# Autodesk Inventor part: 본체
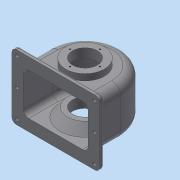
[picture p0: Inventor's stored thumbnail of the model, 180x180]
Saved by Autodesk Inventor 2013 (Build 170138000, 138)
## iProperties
Created: 2015-09
Part Number: 본체
Material: 일반
Document SubType Name: Modeling
Designer: Administrator
Density: 1 g/cm^3
Author: Administrator
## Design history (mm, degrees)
sketch "스케치1"
  geometry: L1 (0, 0)-(0, -47); L2 (0, -47)-(0, 57); L3 (0, -47)-(57, -47); L4 (57, -47)-(57, 0); L5 (0, -47)-(-57, -47); L6 (-57, -47)-(-57, 0); A1 r 57 centre (0, 0) between (57, 0) and (-57, 0)
  constraints: 12 end point, 3 point on circle, 2 perpendicular, 2 tangent, 1 centre point, 1 coincident, 1 collinear, 1 vertical
  dimensions: "d0" = 47 distance of L1.start L1.end; "d1" = 104 distance of L1.end L2.end
extrude "돌출1" new body sketch "스케치1" stored distance "d2" = 77; taper "d3" = 0 deg
fillet "모깎기1" dims "d4" = 14
feature "쉘2" dims "d16" = 5
sketch "스케치5"
  geometry: C1 r 31 at (0, 0); A1 r 43 centre (0, 0) between (43, 0) and (-43, 0) reference
  constraints: 1 centre point, 1 coincident
  dimensions: "d17" = 62 diameter of C1
extrude "돌출4" join sketch "스케치5" distance "d18" = 10; taper "d19" = 0 deg
sketch "스케치6"
  geometry: C1 r 31 at (0, 0) reference; C2 r 20 at (0, 0)
  constraints: 1 centre point, 1 coincident
  dimensions: "d20" = 40 diameter of C2
extrude "돌출5" cut sketch "스케치6" stored distance "d21" = 10; taper "d22" = 0 deg
sketch "스케치7"
  geometry: L1 (-31, 38.5)-(-31, 48.5) reference; L2 (-31, 48.5)-(-20, 48.5) reference; L3 (-20, 48.5)-(-20, 33.5) reference; L4 (-20, 33.5)-(-47, 33.5) reference; L5 (-47, 33.5)-(-47, 38.5) reference; L6 (-47, 38.5)-(-31, 38.5) reference; L7 (57, 24.5)-(57, -24.5) reference; L8 (43, -38.5)-(-47, -38.5) reference; L9 (-47, -38.5)-(-47, -33.5) reference; L10 (-47, -33.5)-(43, -33.5) reference; L11 (52, -24.5)-(52, 24.5) reference; L12 (43, 33.5)-(20, 33.5) reference; L13 (20, 33.5)-(20, 48.5) reference; L14 (20, 48.5)-(31, 48.5) reference; L15 (31, 48.5)-(31, 38.5) reference; L16 (31, 38.5)-(43, 38.5) reference; L17 (0, -19.5)-(28, -19.5); L18 (0, -33.5)-(39.747, -33.5); L19 (28, -19.5)-(39.747, -33.5); L20 (0, -33.5)-(0, -19.5); A1 r 14 centre (43, 24.5) between (57, 24.5) and (43, 38.5) reference; A2 r 14 centre (43, -24.5) between (43, -38.5) and (57, -24.5) reference; A3 r 9 centre (43, -24.5) between (43, -33.5) and (52, -24.5) reference; A4 r 9 centre (43, 24.5) between (52, 24.5) and (43, 33.5) reference; 1 further point
  constraints: 8 end point, 2 point on line, 1 perpendicular
  dimensions: "d24" = 28 distance of L17.start L17.end
revolve "회전1" sketch "스케치7" stored, may be unused: angle "d26" = 90 deg
sketch "스케치8"
  geometry: L1 (-31, 38.5)-(-31, 48.5) reference; L2 (-31, 48.5)-(-20, 48.5) reference; L3 (-20, 48.5)-(-20, 33.5) reference; L4 (-20, 33.5)-(-47, 33.5) reference; L5 (-47, 33.5)-(-47, 38.5) reference; L6 (-47, 38.5)-(-31, 38.5) reference; L7 (57, 24.5)-(57, -24.5) reference; L8 (43, -38.5)-(-47, -38.5) reference; L9 (-47, -38.5)-(-47, -33.5) reference; L10 (-47, -33.5)-(-39.747, -33.5) reference; L11 (-39.747, -33.5)-(-28, -19.5) reference; L12 (-28, -19.5)-(28, -19.5) reference; L13 (28, -19.5)-(39.747, -33.5) reference; L14 (39.747, -33.5)-(43, -33.5) reference; L15 (52, -24.5)-(52, 24.5) reference; L16 (43, 33.5)-(20, 33.5) reference; L17 (20, 33.5)-(20, 48.5) reference; L18 (20, 48.5)-(31, 48.5) reference; L19 (31, 48.5)-(31, 38.5) reference; L20 (31, 38.5)-(43, 38.5) reference; L21 (0, -19.5)-(20, -19.5); L22 (20, -19.5)-(20, -35.5); L23 (20, -35.5)-(0, -35.5); L24 (0, -35.5)-(0, -19.5); A1 r 14 centre (43, 24.5) between (57, 24.5) and (43, 38.5) reference; A2 r 14 centre (43, -24.5) between (43, -38.5) and (57, -24.5) reference; A3 r 9 centre (43, -24.5) between (43, -33.5) and (52, -24.5) reference; A4 r 9 centre (43, 24.5) between (52, 24.5) and (43, 33.5) reference; 1 further point
  constraints: 8 end point, 2 perpendicular, 1 midpoint, 1 parallel, 1 point on line
  dimensions: "d27" = 20 distance of L21.start L21.end; "d28" = 16 distance of L21.end L22.end
revolve "회전2" sketch "스케치8" stored, may be unused: angle "d29" = 90 deg
sketch "스케치9"
  geometry: L1 (-31, 38.5)-(-31, 48.5) reference; L2 (-31, 48.5)-(-20, 48.5) reference; L3 (-20, 48.5)-(-20, 33.5) reference; L4 (-20, 33.5)-(-47, 33.5) reference; L5 (-47, 33.5)-(-47, 38.5) reference; L6 (-47, 38.5)-(-31, 38.5) reference; L7 (57, 24.5)-(57, -24.5) reference; L8 (43, -38.5)-(-47, -38.5) reference; L9 (-47, -38.5)-(-47, -33.5) reference; L10 (-47, -33.5)-(-39.747, -33.5) reference; L11 (-39.747, -33.5)-(-28, -19.5) reference; L12 (-28, -19.5)-(-20, -19.5) reference; L13 (-20, -19.5)-(-20, -35.5) reference; L14 (-20, -35.5)-(20, -35.5) reference; L15 (20, -35.5)-(20, -19.5) reference; L16 (20, -19.5)-(28, -19.5) reference; L17 (28, -19.5)-(39.747, -33.5) reference; L18 (39.747, -33.5)-(43, -33.5) reference; L19 (52, -24.5)-(52, 24.5) reference; L20 (43, 33.5)-(20, 33.5) reference; L21 (20, 33.5)-(20, 48.5) reference; L22 (20, 48.5)-(31, 48.5) reference; L23 (31, 48.5)-(31, 38.5) reference; L24 (31, 38.5)-(43, 38.5) reference; L25 (0, -35.5)-(33, -35.5); L26 (37.416, -38.5)-(33, -33.237); L27 (37.416, -38.5)-(0, -38.5); L28 (0, -35.5)-(0, -38.5); L29 (33, -35.5)-(33, -33.237); L30 (33, -25.459)-(33, -18.456); A1 r 14 centre (43, 24.5) between (57, 24.5) and (43, 38.5) reference; A2 r 14 centre (43, -24.5) between (43, -38.5) and (57, -24.5) reference; A3 r 9 centre (43, -24.5) between (43, -33.5) and (52, -24.5) reference; A4 r 9 centre (43, 24.5) between (52, 24.5) and (43, 33.5) reference; 1 further point
  constraints: 12 end point, 4 point on line, 3 perpendicular, 1 midpoint, 1 parallel
  dimensions: "d30" = 33 distance of L25.start L25.end; "d31" = 5 distance between parallel lines of L17 L26
revolve "회전3" sketch "스케치9" stored, may be unused: angle "d32" = 90 deg
sketch "스케치10"
  geometry: L1 (-14, 14)-(-14, 63) reference; L2 (86, 0)-(0, 0) reference; L3 (100, 14)-(100, 63) reference; L4 (0, 77)-(86, 77) reference; L5 (-27, 90.5)-(113, 90.5); L6 (113, 90.5)-(113, -13.5); L7 (113, -13.5)-(-27, -13.5); L8 (-27, -13.5)-(-27, 90.5); L9 (-27, 90.5)-(113, -13.5); L10 (113, 90.5)-(-27, -13.5); A1 r 14 centre (0, 63) between (0, 77) and (-14, 63) reference; A2 r 14 centre (0, 14) between (-14, 14) and (0, 0) reference; A3 r 14 centre (86, 14) between (86, 0) and (100, 14) reference; A4 r 14 centre (86, 63) between (100, 63) and (86, 77) reference; 1 further point
  constraints: 12 end point, 2 midpoint, 2 parallel, 1 horizontal, 1 perpendicular
  dimensions: "d33" = 140 distance of L6.end L7.end; "d34" = 104 distance of L5.end L6.end
extrude "돌출6" join sketch "스케치10" distance "d35" = 7; taper "d36" = 0 deg
fillet "모깎기2" dims "d37" = 7
fillet "모깎기3" dims "d38" = 1
fillet "모깎기4" dims "d39" = 3
sketch "스케치11"
  geometry: L1 (105, 5.5)-(-19, -82.5); L2 (-19, 5.5)-(105, -82.5); C1 r 2.5 at (-19, 5.5); C2 r 2.5 at (-19, -82.5); C3 r 2.5 at (105, -82.5); C4 r 2.5 at (105, 5.5); C5 r 2.5 at (105, -38.5); C6 r 2.5 at (-19, -38.5); 1 further point
  constraints: 6 centre point, 4 coincident, 4 end point, 2 midpoint
  dimensions: "d40" = 124 distance of L2.end L1.end; "d41" = 88 distance of L1.end L2.start; "d42" = 5 diameter of C1; "d44" = 5 diameter of C3; "d45" = 5 diameter of C4; "d46" = 5 diameter of C5; "d47" = 5 diameter of C6
extrude "돌출7" cut sketch "스케치11" stored distance "d48" = 5 (= d45); taper "d49" = 0 deg
fillet "모깎기5" dims "d50" = 3
sketch "스케치12"
  geometry: L1 (70, -43)-(70, -47) reference; L2 (70, -47)-(64.5, -47) reference; L3 (64.5, -47)-(64.5, -40) reference; L4 (64.5, -40)-(67, -40) reference; L5 (-67, -40)-(-64.5, -40) reference; L6 (-64.5, -40)-(-64.5, -47) reference; L7 (-64.5, -47)-(-70, -47) reference; L8 (-70, -47)-(-70, -43) reference; L9 (-52, 0)-(-52, -47) reference; L10 (-52, -47)-(-59.5, -47) reference; L11 (-59.5, -47)-(-59.5, -40) reference; L12 (-59.5, -40)-(-58, -40) reference; L13 (-57, -39)-(-57, 0) reference; L14 (57, 0)-(57, -39) reference; L15 (58, -40)-(59.5, -40) reference; L16 (59.5, -40)-(59.5, -47) reference; L17 (59.5, -47)-(52, -47) reference; L18 (52, -47)-(52, 0) reference; L19 (0, 63)-(6, 63); L20 (6, 63)-(7.137, 56.551); L21 (0, -47)-(0, 52); L22 (0, 57)-(0, 63); L23 (7.137, 56.551)-(0, 56.551); L24 (0, 56.551)-(0, 57); A1 r 3 centre (67, -43) between (70, -43) and (67, -40) reference; A2 r 3 centre (-67, -43) between (-67, -40) and (-70, -43) reference; A3 r 1 centre (-58, -39) between (-58, -40) and (-57, -39) reference; A4 r 57 centre (0, 0) between (57, 0) and (-57, 0) reference; A5 r 1 centre (58, -39) between (57, -39) and (58, -40) reference; A6 r 52 centre (0, 0) between (52, 0) and (-52, 0) reference; 1 further point
  constraints: 12 end point, 3 perpendicular, 3 point on circle, 2 parallel, 1 collinear
  dimensions: "d51" = 110 distance of L21.start L19.start; "d52" = 6 distance of L19.start L19.end; "d53" = 80 deg angle of L19 L20
revolve "회전4" sketch "스케치12" stored, may be unused: angle "d54" = 90 deg
fillet "모깎기6" dims "d55" = 3
sketch "스케치13"
  geometry: C1 r 6 at (0, 0) reference; 1 further point
  constraints: 1 coincident
hole "구멍1" sketch "스케치13" at (0, 0) diameter "d56" = 4.459; stored, may be unused: countersink angle "d60" = 90 deg, drill point angle "d62" = 118 deg; dims "d57" = 6, "d58" = 4, "d59" = 2, "d61" = 8
sketch "스케치14"
  geometry: C1 r 20 at (0, 0) reference; 1 further point
  dimensions: "d63" = 24 distance of C1.centre point (0, 24)
hole "구멍2" sketch "스케치14" at (0, 24) diameter "d64" = 2.459; stored, may be unused: countersink angle "d68" = 90 deg, drill point angle "d70" = 118 deg; dims "d65" = 6, "d66" = 4, "d67" = 2, "d69" = 8
sketch "스케치15"
  geometry: C1 r 20 at (0, 0) reference; 1 further point
  dimensions: "d74" = 28 distance of C1.centre point (0, 28)
hole "구멍3" sketch "스케치15" at (0, 28) diameter "d75" = 2.459; stored, may be unused: countersink angle "d79" = 90 deg, drill point angle "d81" = 118 deg; dims "d76" = 7, "d77" = 4, "d78" = 2, "d80" = 9
fillet "모깎기7" dims "d85" = 0.5
sketch "스케치16"
  geometry: L1 (76.5, -43)-(76.5, -47) reference; L2 (76.5, -47)-(-27.5, -47) reference; L3 (-27.5, -47)-(-27.5, -43) reference; L4 (-24.5, -40)-(-5.385, -40) reference; L5 (49, -39)-(0, -39) reference; L6 (54.385, -40)-(73.5, -40) reference; L7 (0, -39)-(0, 0) reference; L8 (0, 0)-(49, 0) reference; L9 (49, 0)-(49, -39) reference; A1 r 3 centre (73.5, -43) between (76.5, -43) and (73.5, -40) reference; A2 r 3 centre (-24.5, -43) between (-24.5, -40) and (-27.5, -43) reference; 2 further points
  constraints: 3 other
feature "엠보싱1" sketch "스케치16" dims "d87" = 0.5, "d88" = 0
node "솔리드1"
pattern_circular "원형 패턴1" dims angle "d72" = 360 deg
pattern_circular "원형 패턴2" dims angle "d83" = 360 deg
node "절단 모서리 투영2"
node "절단 모서리 투영3"
node "절단 모서리 투영4"
node "절단 모서리 투영5"
node "절단 모서리 투영6"
